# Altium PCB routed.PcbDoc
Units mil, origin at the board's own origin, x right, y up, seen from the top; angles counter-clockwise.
Board outline 1968.5 x 1181.1 mil, 2 copper layers (Top Layer, Bottom Layer); 4 components, 4 nets, 14 pads, 3 vias.
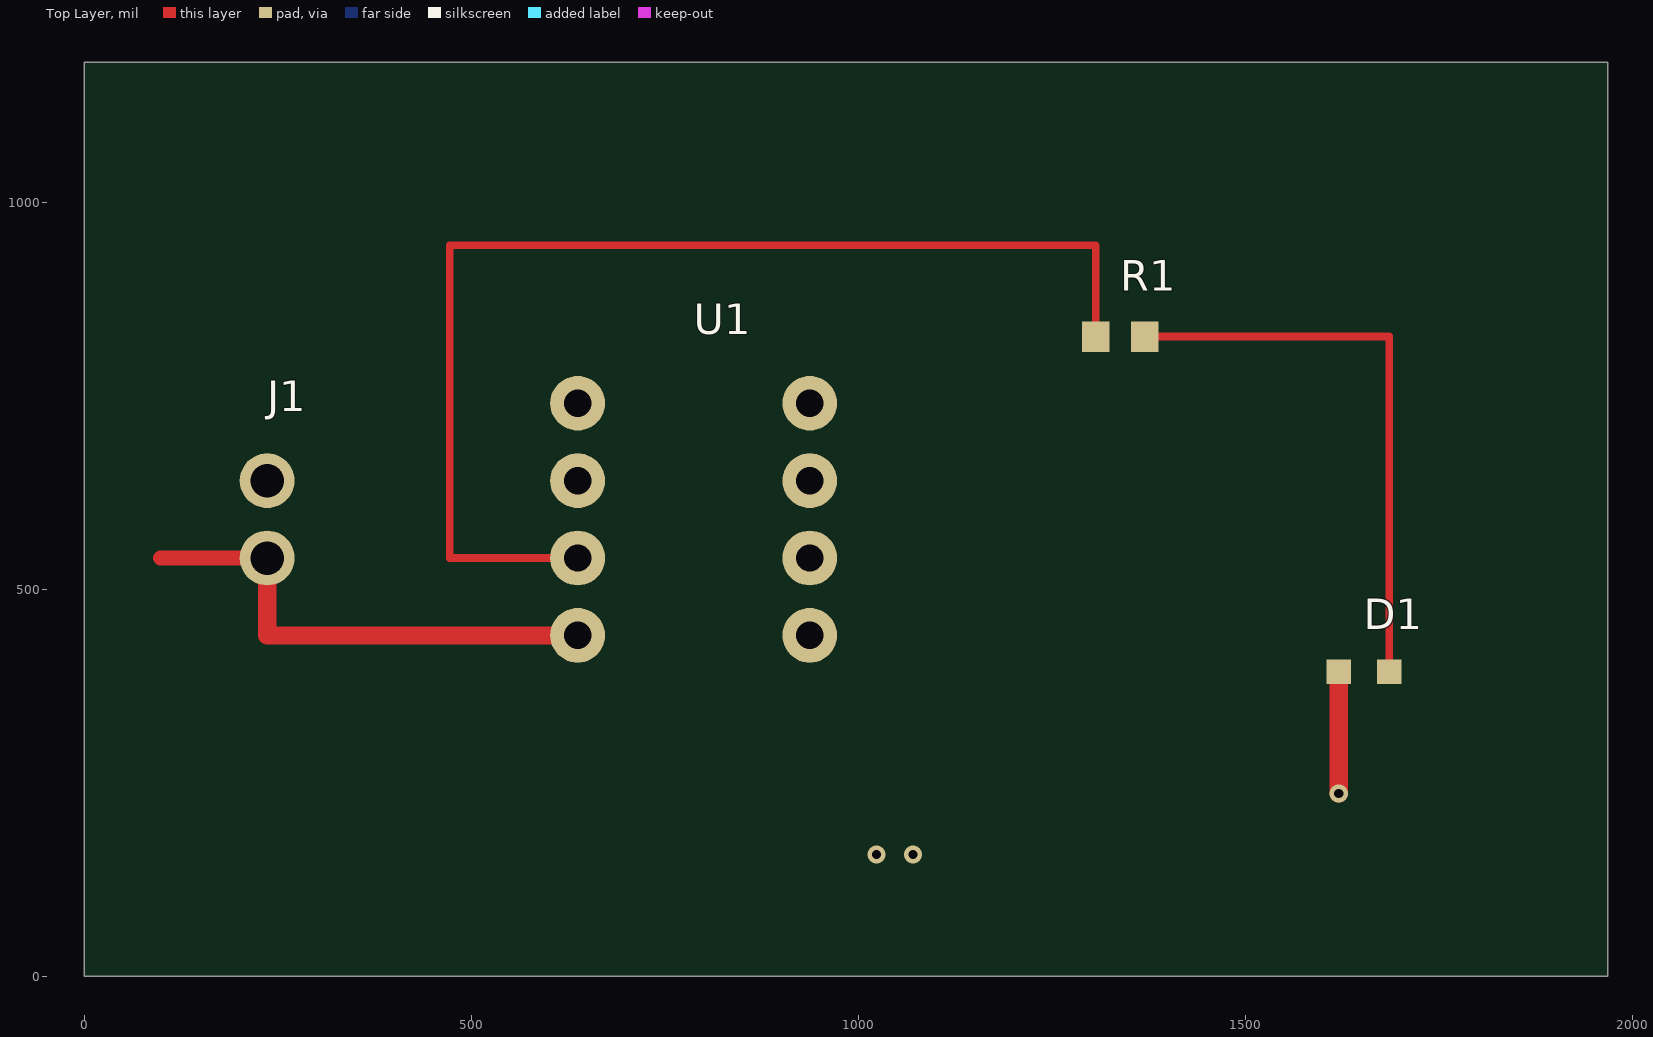
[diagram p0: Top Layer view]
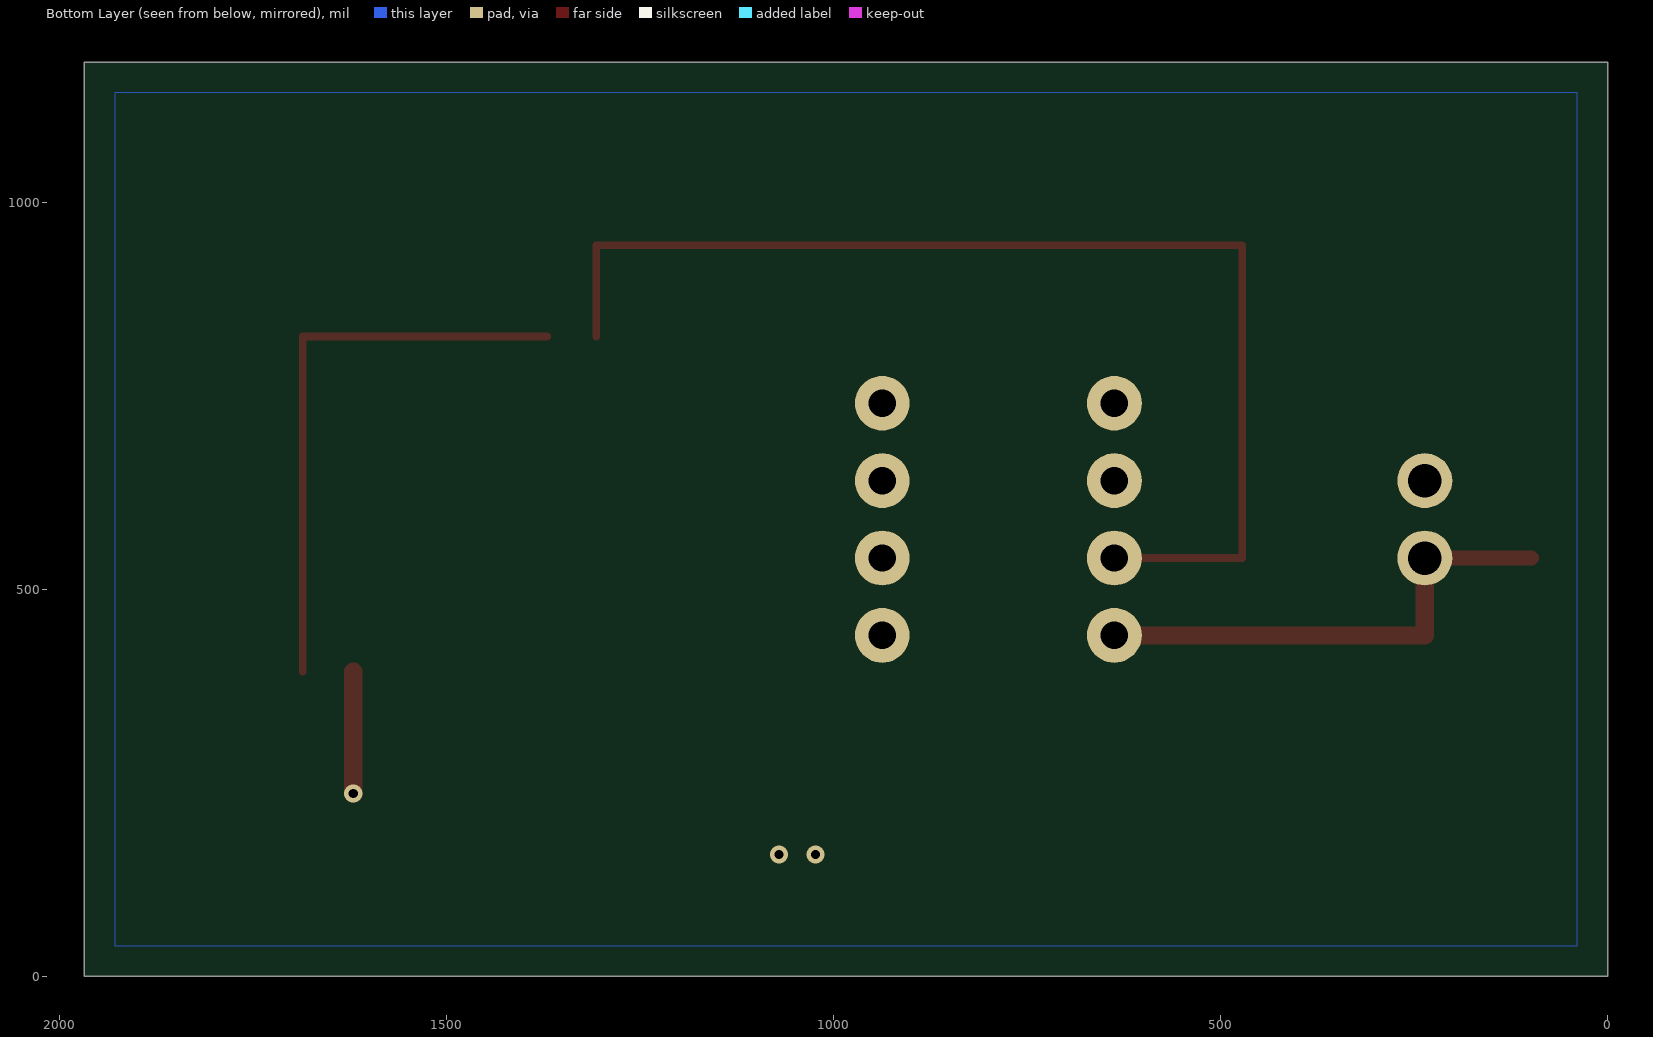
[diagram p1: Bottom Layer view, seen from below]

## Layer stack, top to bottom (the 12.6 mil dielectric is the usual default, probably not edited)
Top Solder: solder mask 0.4, Solder Resist, Dk 3.5
Top Layer: signal copper 1.4
Dielectric 1: dielectric 12.6, FR-4, Dk 4.8
Bottom Layer: signal copper 1.4
Bottom Solder: solder mask 0.4, Solder Resist, Dk 3.5

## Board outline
0,1181.1 1968.5,1181.1 1968.5,0 0,0

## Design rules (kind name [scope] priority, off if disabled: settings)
Clearance Clearance_net_VIN_to_net_LED_A [InNet('VIN') vs InNet('LED_A')] p1: gap=59.06 ignorepadtopadclearanceinfootprint=FALSE
Clearance [All] p2: gap=5.91 ignorepadtopadclearanceinfootprint=FALSE
Clearance Clearance_PWR [InNetClass('PWR')] p3: gap=7.87 ignorepadtopadclearanceinfootprint=FALSE
RoutingVias [All] p1: holewidth=11.81 width=23.62 viastyle="Through Hole" minholewidth=11.81 minwidth=23.62 maxholewidth=11.81 maxwidth=23.62
Width Width_PWR [InNetClass('PWR')] p1: maxlimit=78.74 minlimit=23.62 preferedwidth=23.62
Width [All] p2: maxlimit=78.74 minlimit=5.91 preferedwidth=9.84

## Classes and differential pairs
net class PWR: GND VIN

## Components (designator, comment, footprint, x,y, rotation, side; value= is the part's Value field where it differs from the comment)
D1 "red" LED0603_Kingbright_APT1608SURCK 1653.54,393.7 r0 top
J1 "SUPPLY" Header_1x2_P2.54 236.22,590.55 r0 top
R1 "330" Chip_0603 1338.58,826.77 r0 top
U1 "MCU" DIP8_Microchip_P 787.4,590.55 r0 top locked

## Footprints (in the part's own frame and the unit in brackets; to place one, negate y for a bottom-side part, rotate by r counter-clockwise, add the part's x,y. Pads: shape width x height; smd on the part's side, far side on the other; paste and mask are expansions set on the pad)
Chip_0603 [mm]
  rect 0.9x1 smd: 1(-0.8,0) 2(0.8,0)
DIP8_Microchip_P [mm]
  round 1.8 hole 0.9: 1(-3.81,-3.81) 2(-3.81,-1.27) 3(-3.81,1.27) 4(-3.81,3.81) 5(3.81,3.81) 6(3.81,1.27) 7(3.81,-1.27) 8(3.81,-3.81)
Header_1x2_P2.54 [mm]
  round 1.8 hole 1.1: 1(0,-1.27) 2(0,1.27)
LED0603_Kingbright_APT1608SURCK [mm]
  rect 0.8x0.8 smd: 1(-0.825,0) 2(0.825,0)

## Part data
D1: library part LED
J1: library part Connector_2
R1: library part Resistor
U1: library part Microcontroller

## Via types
v1: diameter 23.62, hole 11.81, Top Layer to Bottom Layer, 3 vias

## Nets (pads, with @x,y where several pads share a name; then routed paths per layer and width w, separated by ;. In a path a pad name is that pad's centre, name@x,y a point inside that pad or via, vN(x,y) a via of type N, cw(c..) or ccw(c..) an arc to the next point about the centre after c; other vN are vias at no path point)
GND: D1.1 J1.2 U1.8 | length 157.5
  Top Layer w23.62: v1(1621.06,236.22) D1.1
LED_A: D1.2 R1.2 | length 749
  Top Layer w9.84: R1.2 1686.02,826.77 D1.2
  other v1: 1070.87,157.48
LED_DRV: R1.1 U1.2 | length 1522
  Top Layer w9.84: U1.2 472.44,540.55 472.44,944.88 1307.09,944.88 R1.1
VIN: J1.1 U1.1 | length 639
  Top Layer w19.68: 98.43,540.55 J1.1
  Top Layer w23.62: J1.1 236.22,440.55 U1.1
  other v1: 1023.62,157.48
pads on no net: U1.3 U1.4 U1.5 U1.6 U1.7

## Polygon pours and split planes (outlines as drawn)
GND on Bottom Layer "GND_L02_P000" (solid, remove dead copper, pour order 0): 39.37,1141.73 1929.13,1141.73 1929.13,39.37 39.37,39.37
